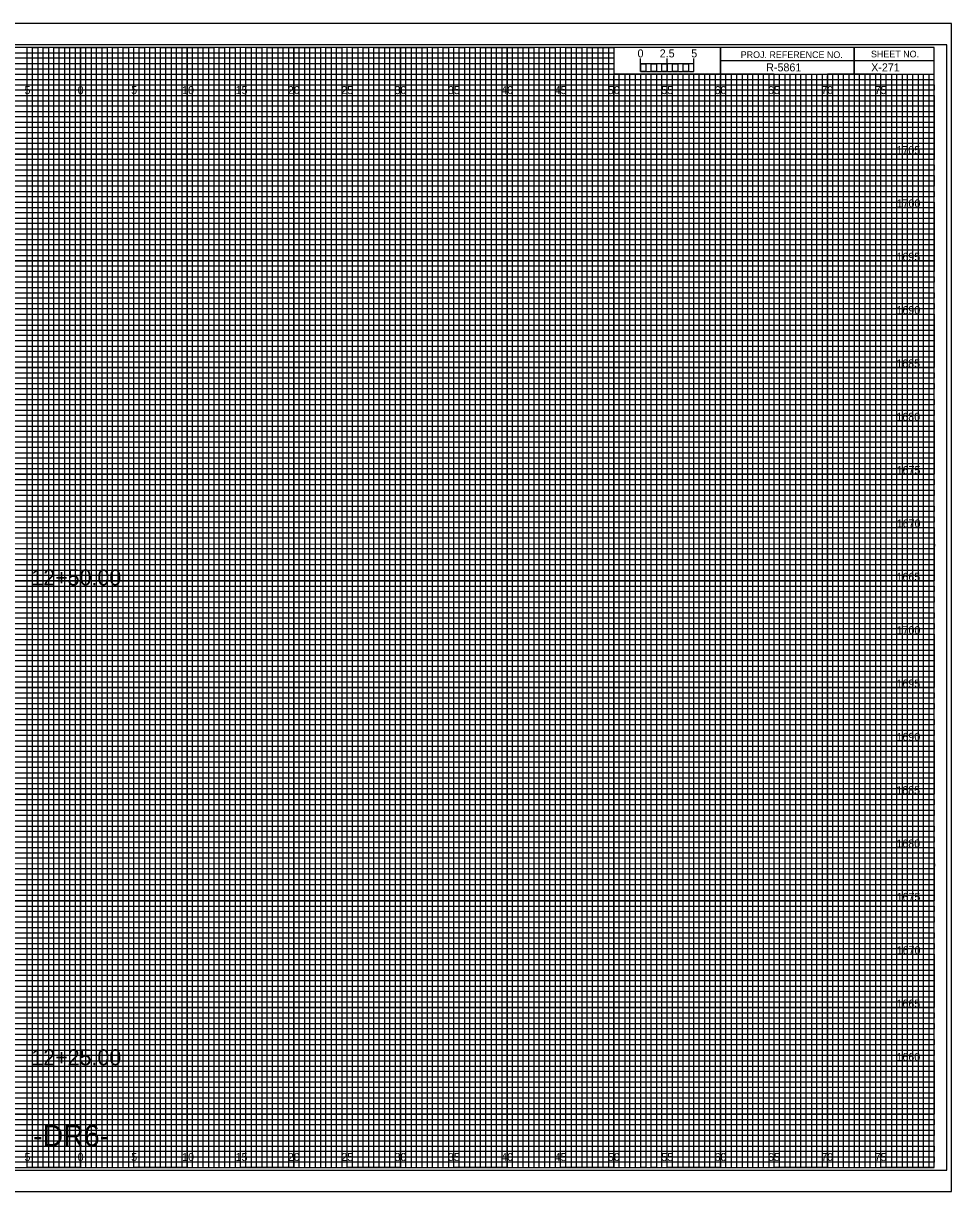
# Model space of a CAD drawing. Extents: x -7 to 162, y -2 to 217.
# Drawn here: x 74.6 to 161.7, y -2.3 to 107.3 of the extents above; entities that cross this region are included whole.
import ezdxf

# ---------------------------------------------------------------- set-up
doc = ezdxf.new("R2010")
doc.units = 0
for name, color, linetype in [('Prop XS Alignment Label', 7, 'Continuous'), ('Prop XS Bar Scale Labels', 7, 'Continuous'), ('Prop XS Elevation Labels', 7, 'Continuous'), ('Prop XS Offset Labels', 7, 'Continuous'), ('Prop XS Project Number', 7, 'Continuous'), ('Prop XS Sheet Number', 7, 'Continuous'), ('Prop XS Station Labels', 7, 'Continuous'), ('Sheet Cross Section CELL', 7, 'Continuous'), ('Sheet Cross Section Grid Major CELL', 7, 'Continuous'), ('Sheet Cross Section Grid Middle CELL', 7, 'Continuous'), ('Sheet Cross Section Grid Minor 1 CELL', 7, 'Continuous'), ('Sheet Cross Section Grid Minor 2 CELL', 7, 'Continuous'), ('Sheet Cross Section Scale CELL', 7, 'Continuous'), ('Sheet Cutting Line CELL', 7, 'Continuous'), ('Sheet DOT Grid CELL', 7, 'Continuous'), ('Sheet Plot Border Inside CELL', 7, 'Continuous'), ('Sheet Plot Border Outside CELL', 7, 'Continuous')]:
    doc.layers.add(name, color=color, linetype=linetype)

msp = doc.modelspace()

# ---------------------------------------------------------------- linework, layer by layer
at = {"layer": 'Sheet Cross Section CELL'}
for p, q in [((152.5, 105), (152.5, 102.5)), ((152.5, 102.5), (152.5, 105)), ((160, 103.75), (140, 103.75)), ((140, 103.75), (140, 102.5)), ((140, 102.5), (160, 102.5))]:
    msp.add_line(p, q, dxfattribs=at)
for points in [[(160, 105), (0, 105), (0, 0), (160, 0)], [(140, 105), (130, 105), (130, 102.52), (140, 102.52)], [(160, 105), (140, 105), (140, 102.5), (160, 102.5)]]:
    msp.add_lwpolyline(points, close=True, dxfattribs=at)
at = {"layer": 'Sheet Cross Section Grid Major CELL'}
for p, q in [((75, 105), (70, 105)), ((75, 0), (75, 105)), ((85, 105), (80, 105)), ((80, 105), (80, 0)), ((85, 0), (85, 105)), ((95, 105), (90, 105)), ((90, 105), (90, 0)), ((95, 0), (95, 105)), ((105, 105), (100, 105)), ((100, 105), (100, 0)), ((105, 0), (105, 105)), ((115, 105), (110, 105)), ((110, 105), (110, 0)), ((115, 0), (115, 105)), ((125, 105), (120, 105)), ((120, 105), (120, 0)), ((125, 0), (125, 105)), ((130, 105), (130, 0)), ((135, 0), (135, 102.5)), ((145, 102.5), (140, 102.5)), ((140, 102.5), (140, 0)), ((145, 0), (145, 102.5)), ((155, 102.5), (150, 102.5)), ((150, 102.5), (150, 0)), ((155, 0), (155, 102.5)), ((80, 0), (75, 0)), ((90, 0), (85, 0)), ((100, 0), (95, 0)), ((110, 0), (105, 0)), ((120, 0), (115, 0)), ((130, 0), (125, 0)), ((140, 0), (135, 0)), ((150, 0), (145, 0)), ((160, 0), (155, 0)), ((160, 0), (160, 0))]:
    msp.add_line(p, q, dxfattribs=at)
for points in [[(0, 100), (160, 100), (160, 95), (0, 95)], [(0, 90), (160, 90), (160, 85), (0, 85)], [(0, 80), (160, 80), (160, 75), (0, 75)], [(0, 70), (160, 70), (160, 65), (0, 65)], [(0, 60), (160, 60), (160, 55), (0, 55)], [(0, 50), (160, 50), (160, 45), (0, 45)], [(0, 40), (160, 40), (160, 35), (0, 35)], [(0, 30), (160, 30), (160, 25), (0, 25)], [(0, 20), (160, 20), (160, 15), (0, 15)], [(0, 10), (160, 10), (160, 5), (0, 5)]]:
    msp.add_lwpolyline(points, dxfattribs=at)
at = {"layer": 'Sheet Cross Section Grid Middle CELL'}
for points in [[(72.5, 0), (77.5, 0), (77.5, 105), (82.5, 105), (82.5, 0), (87.5, 0), (87.5, 105), (92.5, 105), (92.5, 0), (97.5, 0), (97.5, 105), (102.5, 105), (102.5, 0), (107.5, 0), (107.5, 105), (112.5, 105), (112.5, 0), (117.5, 0), (117.5, 105), (122.5, 105), (122.5, 0), (127.5, 0), (127.5, 105), (129.97, 105), (130, 105), (130, 102.5), (132.5, 102.5), (132.5, 0), (137.5, 0), (137.5, 102.5), (142.5, 102.5), (142.5, 0), (147.5, 0), (147.5, 102.5), (152.5, 102.5), (152.5, 0), (157.5, 0), (157.5, 102.5)], [(0, 102.5), (137.5, 102.5)], [(0, 92.5), (160, 92.5), (160, 97.5), (0, 97.5)], [(0, 82.5), (160, 82.5), (160, 87.5), (0, 87.5)], [(0, 72.5), (160, 72.5), (160, 77.5), (0, 77.5)], [(0, 62.5), (160, 62.5), (160, 67.5), (0, 67.5)], [(0, 52.5), (160, 52.5), (160, 57.5), (0, 57.5)], [(0, 42.5), (160, 42.5), (160, 47.5), (0, 47.5)], [(0, 32.5), (160, 32.5), (160, 37.5), (0, 37.5)], [(0, 22.5), (160, 22.5), (160, 27.5), (0, 27.5)], [(0, 12.5), (160, 12.5), (160, 17.5), (0, 17.5)], [(0, 2.5), (160, 2.5), (160, 7.5), (0, 7.5)]]:
    msp.add_lwpolyline(points, dxfattribs=at)
at = {"layer": 'Sheet Cross Section Grid Minor 1 CELL'}
for p, q in [((0, 104.5), (130, 104.5)), ((130, 104.5), (130, 103.99)), ((130, 103.99), (0, 103.99)), ((0, 103.5), (130, 103.5)), ((130, 102.95), (0, 102.95)), ((130, 103.5), (130, 102.95)), ((0, 102), (160, 102))]:
    msp.add_line(p, q, dxfattribs=at)
for points in [[(0, 101.5), (135, 101.5), (160, 101.5), (160, 101), (0, 101)], [(0, 100.5), (160, 100.5), (160, 99.5), (0, 99.5)], [(0, 99), (160, 99), (160, 98.5), (0, 98.49)], [(0, 98), (160, 98), (160, 97), (0, 97)], [(0, 96.5), (160, 96.5), (160, 96), (0, 96)], [(0, 95.5), (160, 95.5), (160, 94.5), (0, 94.5)], [(0, 94), (160, 94), (160, 93.5), (0, 93.5)], [(0, 93), (160, 93), (160, 92), (0, 92)], [(0, 91.5), (160, 91.5), (160, 91), (0, 91)], [(0, 90.5), (160, 90.5), (160, 89.5), (0, 89.5)], [(0, 89), (160, 89), (160, 88.5), (0, 88.5)], [(0, 88), (160, 88), (160, 86.98), (160, 86.5), (160, 86), (0, 86)], [(0, 87), (160, 87), (160, 86.5), (0, 86.5)], [(0, 85.5), (160, 85.5), (160, 84.5), (0, 84.52)], [(0, 84.52), (160, 84.5), (160, 84), (0, 84)], [(0, 83.5), (160, 83.5), (160, 83), (0, 83)], [(0, 82), (160, 82), (160, 81.5), (0, 81.5)], [(0, 81), (160, 81), (160, 80.5), (0, 80.5)], [(-0.04, 79.45), (160, 79.45), (160, 78.94), (-0.04, 78.94)], [(0, 78.5), (160, 78.5), (160, 78), (0, 78)], [(0, 77), (160, 77), (160, 76.5), (0, 76.5)], [(0, 76), (160, 76), (160, 75.5), (0, 75.5)], [(0, 74.5), (160, 74.5), (160, 74), (0, 74)], [(0, 73.5), (160, 73.5), (160, 73), (0, 73)], [(0, 72), (160, 72), (160, 71.5), (0, 71.5)], [(0, 71), (160, 71), (160, 70.5), (0, 70.5)], [(0, 69.5), (160, 69.5), (160, 68.99), (0, 69)], [(0, 68.5), (160, 68.5), (160, 68), (0, 68)], [(0, 67), (160, 67), (160, 66.5), (0, 66.5)], [(0, 66), (160, 66), (160, 65.5), (0, 65.5)], [(0, 64.5), (160, 64.5), (160, 64), (0, 64)], [(0, 63.5), (160, 63.5), (160, 63), (0, 63)], [(0, 62), (160, 62), (160, 61.5), (0, 61.5)], [(0, 61), (160, 61), (160, 60.5), (0, 60.5)], [(0, 59.5), (160, 59.5), (160, 59), (0, 59)], [(0, 58.5), (160.03, 58.45), (160, 58), (0, 58)], [(0, 57), (160, 57), (160, 56.5), (0, 56.5)], [(0, 56), (160, 56), (160, 55.5), (0, 55.5)], [(0, 54.5), (160, 54.5), (160, 54), (0, 54)], [(0, 53.5), (160, 53.5), (160, 53), (0, 53)], [(0, 52), (160, 52), (160, 51.5), (0, 51.5)], [(0, 51), (160, 51), (160, 50.5), (0, 50.5)], [(0, 49.5), (160, 49.5), (160, 49), (0, 49)], [(0, 48.5), (160, 48.5), (160, 48), (0, 48)], [(0, 47), (160, 47), (160, 46.5), (0, 46.5)], [(0, 46), (160, 46), (160, 45.5), (0, 45.5)], [(0, 44.5), (160, 44.5), (160, 44), (0, 44)], [(0, 43.5), (160, 43.5), (160, 43), (0, 43)], [(0, 42), (160, 42), (160, 41.5), (0, 41.5)], [(0, 41), (160, 41), (160, 40.5), (0, 40.5)], [(0, 39.5), (160, 39.5), (160, 38.99), (0, 39)], [(0, 38.5), (160, 38.5), (160, 38), (0, 38)], [(0, 37), (160, 37), (160, 36.5), (0, 36.5)], [(0, 36), (160, 36), (160, 35.5), (0, 35.5)], [(0, 34.5), (160, 34.5), (160, 34), (0, 34)], [(0, 33.5), (160, 33.5), (160, 33), (0, 33)], [(0, 32), (160, 32), (160, 31.5), (0, 31.5)], [(0, 31), (160, 31), (160, 30.5), (0, 30.5)], [(0, 29.5), (160, 29.5), (160, 29), (0, 29)], [(0, 28.5), (160.03, 28.46), (160, 28), (0, 28)], [(0, 27), (160, 27), (160, 26.5), (0, 26.5)], [(0, 26), (160, 26), (160, 25.5), (0, 25.5)], [(0, 24.5), (160, 24.5), (160, 24), (0, 24)], [(0, 23.5), (160, 23.5), (160, 23), (0, 23)], [(0, 22), (160, 22), (160, 21.5), (0, 21.5)], [(0, 21), (160, 21), (160, 20.5), (0, 20.5)], [(0, 19.5), (160, 19.5), (160, 19), (0, 19)], [(0, 18.5), (160, 18.5), (160, 18), (0, 18)], [(0, 17), (160, 17), (160, 16.5), (0, 16.5)], [(0, 16), (160, 16), (160, 15.5), (0, 15.5)], [(0, 14.5), (160, 14.5), (160, 14), (0, 14)], [(0, 13.5), (160, 13.5), (160, 13), (0, 13)], [(0, 12), (160, 12), (160, 11.5), (0, 11.5)], [(0, 11), (160, 11), (160, 10.5), (0, 10.5)], [(0, 9.5), (160, 9.5), (160, 9), (0, 9)], [(0, 8.5), (160, 8.5), (160, 8), (0, 8)], [(0, 7), (160, 7), (160, 6.5), (0, 6.5)], [(0, 6), (160, 6), (160, 5.5), (0, 5.5)], [(0, 4.5), (160, 4.5), (160, 4), (0, 4)], [(0, 3.5), (160, 3.5), (160, 3), (0, 3)], [(0, 2), (160, 2), (160, 1.5), (0, 1.5)], [(0, 1), (160, 1), (160, 0.5), (0, 0.5)]]:
    msp.add_lwpolyline(points, dxfattribs=at)
at = {"layer": 'Sheet Cross Section Grid Minor 2 CELL'}
for p, q in [((133.5, 102.5), (133, 102.5)), ((133, 102.5), (133, 0)), ((133.5, 0), (133.5, 102.5)), ((134.5, 102.5), (134, 102.5)), ((134, 102.5), (134, 0)), ((134.5, 0), (134.5, 102.5)), ((133, 0), (132.5, 0)), ((134, 0), (133.5, 0))]:
    msp.add_line(p, q, dxfattribs=at)
for points in [[(75, 0), (75.5, 0), (75.5, 105), (76, 105), (76, 0)], [(76, 0), (76.5, 0), (76.5, 105), (77, 105), (77, 0)], [(77.5, 0), (78, 0), (78, 105), (78.5, 105), (78.5, 0)], [(78.5, 0), (79, 0), (79, 105), (79.5, 105), (79.5, 0)], [(80, 0), (80.5, 0), (80.5, 105), (81, 105), (81, 0)], [(81, 0), (81.5, 0), (81.5, 105), (82, 105), (82, 0)], [(82.5, 0), (83, 0), (83, 105), (83.5, 105), (83.5, 0)], [(83.5, 0), (84, 0), (84, 105), (84.5, 105), (84.5, 0)], [(85, 0), (85.5, 0), (85.5, 105), (86, 105), (86, 0)], [(86, 0), (86.5, 0), (86.5, 105), (87, 105), (87, 0)], [(87.5, 0), (88, 0), (88, 105), (88.5, 105), (88.5, 0)], [(88.5, 0), (89, 0), (89, 105), (89.5, 105), (89.5, 0)], [(90, 0), (90.5, 0), (90.5, 105), (91, 105), (91, 0)], [(91, 0), (91.5, 0), (91.5, 105), (92, 105), (92, 0)], [(92.5, 0), (93, 0), (93, 105), (93.5, 105), (93.5, 0)], [(93.5, 0), (94, 0), (94, 105), (94.5, 105), (94.5, 0)], [(95, 0), (95.5, 0), (95.5, 105), (96, 105), (96, 0)], [(96, 0), (96.5, 0), (96.5, 105), (97, 105), (97, 0)], [(97.5, 0), (98, 0), (98, 105), (98.5, 105), (98.5, 0)], [(98.5, 0), (99, 0), (99, 105), (99.5, 105), (99.5, 0)], [(100, 0), (100.5, 0), (100.5, 105), (101, 105), (101, 0)], [(101, 0), (101.5, 0), (101.5, 105), (102, 105), (102, 0)], [(102.5, 0), (103, 0), (103, 105), (103.5, 105), (103.5, 0)], [(103.5, 0), (104, 0), (104, 105), (104.5, 105), (104.5, 0)], [(105, 0), (105.5, 0), (105.5, 105), (106, 105), (106, 0)], [(106, 0), (106.5, 0), (106.5, 105), (107, 105), (107, 0)], [(107.5, 0), (108, 0), (108, 105), (108.5, 105), (108.5, 0)], [(108.5, 0), (109, 0), (109, 105), (109.5, 105), (109.5, 0)], [(110, 0), (110.5, 0), (110.5, 105), (111, 105), (111, 0)], [(111, 0), (111.5, 0), (111.5, 105), (112, 105), (112, 0)], [(112.5, 0), (113, 0), (113, 105), (113.5, 105), (113.5, 0)], [(113.5, 0), (114, 0), (114, 105), (114.5, 105), (114.5, 0)], [(115, 0), (115.5, 0), (115.5, 105), (116, 105), (116, 0)], [(116, 0), (116.5, 0), (116.5, 105), (117, 105), (117, 0)], [(117.5, 0), (118, 0), (118, 105), (118.5, 105), (118.5, 0)], [(118.5, 0), (119, 0), (119, 105), (119.5, 105), (119.5, 0)], [(120, 0), (120.5, 0), (120.5, 105), (121, 105), (121, 0)], [(121, 0), (121.5, 0), (121.5, 105), (122, 105), (122, 0)], [(122.5, 0), (123, 0), (123, 105), (123.5, 105), (123.5, 0)], [(123.5, 0), (124, 0), (124, 105), (124.5, 105), (124.5, 0)], [(125, 0), (125.5, 0), (125.5, 105), (126, 105), (126, 0)], [(126, 0), (126.5, 0), (126.5, 105), (127, 105), (127, 0)], [(127.5, 0), (128, 0), (128, 105), (128.5, 105), (128.5, 0)], [(128.5, 0), (129, 0), (129, 105), (129.5, 105), (129.5, 0)], [(130, 0), (130.5, 0), (130.5, 102.5), (131.01, 102.5), (131.01, 0)], [(131, 0), (131.5, 0), (131.5, 102.5), (132, 102.5), (132, 0)], [(135, 0), (135.49, 0), (135.49, 102.5), (136, 102.5), (136, 0)], [(136, 0), (136.5, 0), (136.5, 102.5), (137.03, 102.5), (137.03, 0)], [(137.5, 0), (138, 0), (138, 102.5), (138.5, 102.5), (138.5, 0)], [(138.5, 0), (139, 0), (139, 102.5), (139.5, 102.5), (139.5, 0)], [(140, 0), (140.5, 0), (140.5, 102.5), (141, 102.5), (141, 0)], [(141, 0), (141.5, 0), (141.5, 102.5), (142, 102.5), (142, 0)], [(142.5, 0), (143, 0), (143, 102.5), (143.5, 102.5), (143.5, 0)], [(143.5, 0), (144, 0), (144, 102.5), (144.5, 102.5), (144.5, 0)], [(145, 0), (145.5, 0), (145.5, 102.5), (146, 102.5), (146, 0)], [(146, 0), (146.5, 0), (146.5, 102.5), (147, 102.5), (147, 0)], [(147.5, 0), (148, 0), (148, 102.5), (148.5, 102.5), (148.5, 0)], [(148.5, 0), (149, 0), (149, 102.5), (149.5, 102.5), (149.5, 0)], [(150, 0), (150.5, 0), (150.5, 102.5), (151, 102.5), (151, 0)], [(151, 0), (151.5, 0), (151.5, 102.5), (152, 102.5), (152, 0)], [(152.5, 0), (153, 0), (153, 102.5), (153.5, 102.5), (153.5, 0)], [(153.5, 0), (154, 0), (154, 102.5), (154.5, 102.5), (154.5, 0)], [(155, 0), (155.5, 0), (155.5, 102.5), (156, 102.5), (156, 0)], [(156, 0), (156.5, 0), (156.5, 102.5), (157, 102.5), (157, 0)], [(157.5, 0), (158, 0), (158, 102.5), (158.5, 102.5), (158.5, 0)], [(158.5, 0), (159, 0), (159, 102.5), (159.5, 102.5), (159.5, 0)]]:
    msp.add_lwpolyline(points, dxfattribs=at)
at = {"layer": 'Sheet Cross Section Scale CELL'}
for p, q in [((132.5, 102.75), (132.5, 103.95)), ((132.5, 103.45), (132.5, 103.95)), ((135, 102.75), (135, 103.95)), ((137.5, 102.75), (137.5, 103.95)), ((137.5, 103.45), (137.5, 103.95))]:
    msp.add_line(p, q, dxfattribs=at)
for points in [[(137.5, 103.45), (132.5, 103.45), (132.5, 102.75), (137.5, 102.75)], [(132.5, 103.45), (133, 103.45), (133, 102.75), (132.5, 102.75)], [(133.5, 103.45), (134, 103.45), (134, 102.75), (133.5, 102.75)], [(134.5, 103.45), (135, 103.45), (135, 102.75), (134.5, 102.75)], [(135.5, 103.45), (136, 103.45), (136, 102.75), (135.5, 102.75)], [(136.5, 103.45), (137, 103.45), (137, 102.75), (136.5, 102.75)]]:
    msp.add_lwpolyline(points, close=True, dxfattribs=at)
at = {"layer": 'Sheet Cutting Line CELL'}
for p, q in [((161.65, 107.25), (-6.7, 107.25)), ((-6.7, -2.25), (161.65, -2.25))]:
    msp.add_line(p, q, dxfattribs=at)
at = {"layer": 'Sheet DOT Grid CELL'}
for p, q in [((75, 0), (75, 105)), ((80, 0), (80, 105)), ((85, 0), (85, 105)), ((90, 0), (90, 105)), ((95, 0), (95, 105)), ((100, 0), (100, 105)), ((105, 0), (105, 105)), ((110, 0), (110, 105)), ((115, 0), (115, 105)), ((120, 0), (120, 105)), ((125, 0), (125, 105)), ((130, 0), (130, 102.34)), ((135, 0), (135, 102.34)), ((140, 0), (140, 102.34)), ((145, 0), (145, 102.34)), ((150, 0), (150, 102.34)), ((155, 0), (155, 102.34)), ((0, 100), (160, 100)), ((0, 95), (160, 95)), ((0, 90), (160, 90)), ((0, 85), (160, 85)), ((0, 80), (160, 80)), ((0, 75), (160, 75)), ((0, 70), (160, 70)), ((0, 65), (160, 65)), ((0, 60), (160, 60)), ((0, 55), (160, 55)), ((0, 50), (160, 50)), ((0, 45), (160, 45)), ((0, 40), (160, 40)), ((0, 35), (160, 35)), ((0, 30), (160, 30)), ((0, 25), (160, 25)), ((0, 20), (160, 20)), ((0, 15), (160, 15)), ((0, 10), (160, 10)), ((0, 5), (160, 5))]:
    msp.add_line(p, q, dxfattribs=at)
at = {"layer": 'Sheet Plot Border Inside CELL'}
msp.add_lwpolyline([(-5.4, -0.25), (161.2, -0.25), (161.2, 105.25), (-5.4, 105.25)], close=True, dxfattribs=at)
at = {"layer": 'Sheet Plot Border Outside CELL'}
msp.add_lwpolyline([(-6.7, -2.25), (161.65, -2.25), (161.65, 107.25), (-6.7, 107.25)], close=True, dxfattribs=at)

# ---------------------------------------------------------------- texts
at = {"layer": 'Prop XS Alignment Label'}
msp.add_text('-DR6-', height=2, dxfattribs=at).set_placement((75.55, 2))
at = {"layer": 'Prop XS Bar Scale Labels'}
for s, p in [('2.5', (134.29, 104.06)), ('5', (137.24, 104.06))]:
    msp.add_text(s, height=0.75, dxfattribs=at).set_placement(p)
at = {"layer": 'Prop XS Elevation Labels'}
for s, p in [('1705', (156.48, 95)), ('1700', (156.49, 90)), ('1695', (156.48, 85)), ('1690', (156.48, 80)), ('1685', (156.46, 75)), ('1680', (156.47, 70)), ('1675', (156.49, 65)), ('1670', (156.5, 60)), ('1665', (156.48, 55)), ('1700', (156.49, 50)), ('1695', (156.48, 45)), ('1690', (156.48, 40)), ('1685', (156.46, 35)), ('1680', (156.47, 30)), ('1675', (156.49, 25)), ('1670', (156.5, 20)), ('1665', (156.48, 15)), ('1660', (156.48, 10))]:
    msp.add_text(s, height=0.75, dxfattribs=at).set_placement(p)
at = {"layer": 'Prop XS Offset Labels'}
for s, p in [('5', (74.74, 100.62)), ('0', (79.73, 100.62)), ('0', (79.73, 100.62)), ('5', (84.74, 100.62)), ('10', (89.52, 100.62)), ('15', (94.53, 100.62)), ('20', (99.43, 100.62)), ('25', (104.44, 100.62)), ('30', (109.43, 100.62)), ('35', (114.44, 100.62)), ('40', (119.43, 100.62)), ('45', (124.44, 100.62)), ('50', (129.43, 100.62)), ('55', (134.44, 100.62)), ('60', (139.43, 100.62)), ('65', (144.44, 100.62)), ('70', (149.43, 100.62)), ('75', (154.44, 100.62)), ('5', (74.74, 0.62)), ('0', (79.73, 0.62)), ('0', (79.73, 0.62)), ('5', (84.74, 0.62)), ('10', (89.52, 0.62)), ('15', (94.53, 0.62)), ('20', (99.43, 0.62)), ('25', (104.44, 0.62)), ('30', (109.43, 0.62)), ('35', (114.44, 0.62)), ('40', (119.43, 0.62)), ('45', (124.44, 0.62)), ('50', (129.43, 0.62)), ('55', (134.44, 0.62)), ('60', (139.43, 0.62)), ('65', (144.44, 0.62)), ('70', (149.43, 0.62)), ('75', (154.44, 0.62))]:
    msp.add_text(s, height=0.75, dxfattribs=at).set_placement(p)
at = {"layer": 'Prop XS Project Number'}
msp.add_text('R-5861', height=0.75, dxfattribs=at).set_placement((144.27, 102.75))
at = {"layer": 'Prop XS Sheet Number'}
msp.add_text('X-271', height=0.75, dxfattribs=at).set_placement((154.11, 102.75))
at = {"layer": 'Prop XS Station Labels'}
for s, p in [('12+50.00', (75.39, 54.57)), ('12+25.00', (75.39, 9.59))]:
    msp.add_text(s, height=1.5, dxfattribs=at).set_placement(p)
at = {"layer": 'Sheet Cross Section CELL'}
for s, p in [('PROJ. REFERENCE NO.', (141.88, 104)), ('SHEET NO.', (154.09, 104.06))]:
    msp.add_text(s, height=0.625, dxfattribs=at).set_placement(p)
at = {"layer": 'Sheet Cross Section Scale CELL'}
msp.add_text('0', height=0.75, dxfattribs=at).set_placement((132.21, 104.06))

doc.saveas('drawing.dxf')
